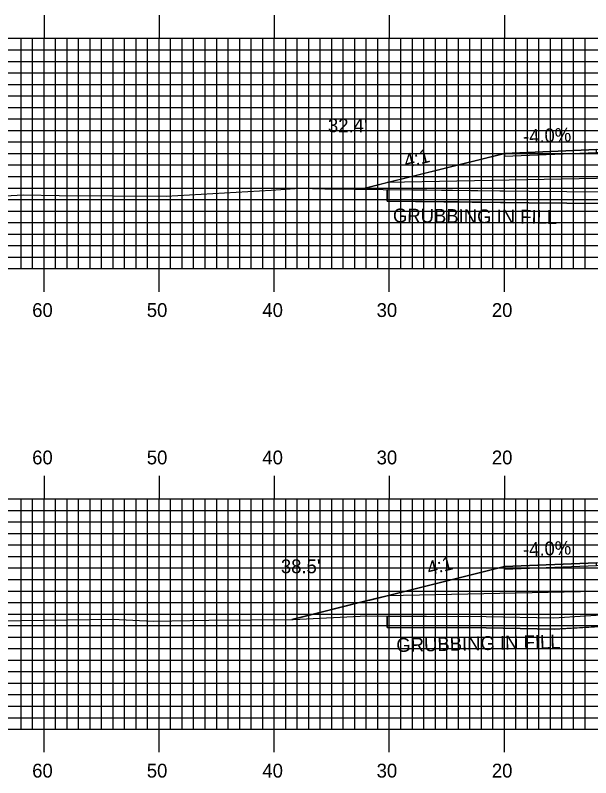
# Model space of a CAD drawing. Extents: x 1777925 to 1778268, y 442591 to 442811.
# Drawn here: x 1778028.3 to 1778078.3, y 442689.4 to 442755.7 of the extents above; entities that cross this region are included whole.
import ezdxf

# ---------------------------------------------------------------- set-up
doc = ezdxf.new("R2010")
doc.units = 0
for name, color, linetype in [('ANNOTATION', 7, 'Continuous'), ('D_Roadway_Centerline', 7, 'Continuous'), ('D_Roadway_Edge_Shoulder', 7, 'Continuous'), ('D_Roadway_SlopeLines', 7, 'Continuous'), ('D_Roadway_SubGrade', 7, 'Continuous'), ('D_Text_Standard', 7, 'Continuous'), ('GRUBBING IN FILL', 7, 'Continuous'), ('H_V ANNOTATION', 7, 'Continuous'), ('MAJOR', 7, 'Continuous'), ('MINOR', 7, 'Continuous'), ('S_Roadway_Centerline', 7, 'Continuous')]:
    doc.layers.add(name, color=color, linetype=linetype)

msp = doc.modelspace()

# ---------------------------------------------------------------- linework, layer by layer
at = {"layer": 'D_Roadway_Centerline'}
for points in [[(1778058.344, 442740.566), (1778060.616, 442741.134), (1778070.79, 442743.677), (1778078.79, 442743.997), (1778090.789, 442744.237), (1778090.79, 442744.237), (1778097.486, 442744.103), (1778102.79, 442743.997), (1778107.608, 442743.804), (1778110.79, 442743.677), (1778120.964, 442741.134), (1778124.306, 442740.299)], [(1778054.753, 442740.615), (1778054.761, 442740.615)], [(1778052.326, 442703.186), (1778053.506, 442703.481), (1778058.79, 442704.802), (1778059.096, 442704.879), (1778060.616, 442705.259), (1778065.395, 442706.454), (1778070.79, 442707.802), (1778078.79, 442708.122), (1778088.92, 442708.325), (1778090.79, 442708.362), (1778102.79, 442708.122), (1778108.283, 442707.902), (1778110.79, 442707.802), (1778120.964, 442705.259), (1778126.218, 442703.946)]]:
    msp.add_lwpolyline(points, dxfattribs=at)
at = {"layer": 'D_Roadway_Edge_Shoulder'}
for points in [[(1778078.79, 442743.997), (1778070.79, 442743.677), (1778070.79, 442743.427), (1778078.79, 442743.747)], [(1778078.79, 442708.122), (1778070.79, 442707.802), (1778070.79, 442707.552), (1778078.79, 442707.872)]]:
    msp.add_lwpolyline(points, close=True, dxfattribs=at)
at = {"layer": 'D_Roadway_SlopeLines'}
for points in [[(1778070.79, 442743.677), (1778058.344, 442740.566)], [(1778070.79, 442707.802), (1778060.616, 442705.259), (1778058.79, 442704.802), (1778052.326, 442703.186)]]:
    msp.add_lwpolyline(points, dxfattribs=at)
at = {"layer": 'D_Roadway_SubGrade'}
for points in [[(1778078.79, 442741.497), (1778060.616, 442741.134), (1778070.79, 442743.677), (1778070.79, 442743.427), (1778078.79, 442743.747), (1778090.79, 442743.987), (1778102.79, 442743.747), (1778110.79, 442743.427), (1778110.79, 442743.677), (1778120.964, 442741.134), (1778102.79, 442741.497), (1778090.79, 442741.737)], [(1778078.79, 442705.622), (1778060.616, 442705.259), (1778070.79, 442707.802), (1778070.79, 442707.552), (1778078.79, 442707.872), (1778090.79, 442708.112), (1778102.79, 442707.872), (1778110.79, 442707.552), (1778110.79, 442707.802), (1778120.964, 442705.259), (1778102.79, 442705.622), (1778090.79, 442705.862)]]:
    msp.add_lwpolyline(points, close=True, dxfattribs=at)
at = {"layer": 'GRUBBING IN FILL'}
for p, q in [((1778060.616, 442740.537), (1778060.616, 442739.537)), ((1778060.616, 442740.537), (1778060.616, 442739.537)), ((1778060.616, 442703.49), (1778060.616, 442702.49)), ((1778060.616, 442703.49), (1778060.616, 442702.49))]:
    msp.add_line(p, q, dxfattribs=at)
for points in [[(1778060.616, 442740.537), (1778064.057, 442740.494), (1778072.934, 442740.381), (1778076.219, 442740.352), (1778079.504, 442740.324), (1778083.5, 442740.316), (1778087.496, 442740.308), (1778090.79, 442740.292), (1778090.79, 442739.292), (1778087.492, 442739.308), (1778076.211, 442739.352), (1778072.923, 442739.381), (1778066.77, 442739.459), (1778060.616, 442739.537)], [(1778060.616, 442740.537), (1778064.057, 442740.494), (1778072.934, 442740.381), (1778076.219, 442740.352), (1778079.504, 442740.324), (1778083.5, 442740.316), (1778087.496, 442740.308), (1778090.79, 442740.292), (1778090.79, 442739.292), (1778087.492, 442739.308), (1778076.211, 442739.352), (1778072.923, 442739.381), (1778066.77, 442739.459), (1778060.616, 442739.537)], [(1778060.616, 442702.49), (1778060.616, 442703.49), (1778064.022, 442703.478), (1778069.212, 442703.46), (1778075.082, 442703.34), (1778080.576, 442703.67), (1778085.956, 442703.697), (1778090.79, 442703.721), (1778090.79, 442702.721), (1778085.958, 442702.697), (1778080.608, 442702.67), (1778077.855, 442702.505), (1778075.101, 442702.339), (1778072.151, 442702.4), (1778069.2, 442702.46)], [(1778060.616, 442702.49), (1778060.616, 442703.49), (1778064.022, 442703.478), (1778069.212, 442703.46), (1778075.082, 442703.34), (1778080.576, 442703.67), (1778085.956, 442703.697), (1778090.79, 442703.721), (1778090.79, 442702.721), (1778085.958, 442702.697), (1778080.608, 442702.67), (1778077.855, 442702.505), (1778075.101, 442702.339), (1778072.151, 442702.4), (1778069.2, 442702.46)]]:
    msp.add_lwpolyline(points, close=True, dxfattribs=at)
for points in [[(1778060.616, 442739.537), (1778072.923, 442739.381), (1778079.499, 442739.324), (1778087.492, 442739.308), (1778097.437, 442739.262), (1778101.244, 442739.246), (1778110.991, 442739.24), (1778120.964, 442739.288)], [(1778060.616, 442739.537), (1778072.923, 442739.381), (1778079.499, 442739.324), (1778087.492, 442739.308), (1778097.437, 442739.262), (1778101.244, 442739.246), (1778110.991, 442739.24), (1778120.964, 442739.288)], [(1778060.616, 442702.49), (1778069.2, 442702.46), (1778075.101, 442702.339), (1778080.608, 442702.67), (1778091.308, 442702.724), (1778097.749, 442702.34), (1778103.966, 442702.493), (1778110.139, 442702.686), (1778116.078, 442702.822), (1778120.964, 442702.882)], [(1778060.616, 442702.49), (1778069.2, 442702.46), (1778075.101, 442702.339), (1778080.608, 442702.67), (1778091.308, 442702.724), (1778097.749, 442702.34), (1778103.966, 442702.493), (1778110.139, 442702.686), (1778116.078, 442702.822), (1778120.964, 442702.882)]]:
    msp.add_lwpolyline(points, dxfattribs=at)
at = {"layer": 'MAJOR'}
for p, q in [((1778030.79, 442755.669), (1778030.79, 442753.665)), ((1778040.79, 442755.669), (1778040.79, 442753.665)), ((1778050.79, 442755.669), (1778050.79, 442753.665)), ((1778060.79, 442755.669), (1778060.79, 442753.665)), ((1778070.79, 442755.669), (1778070.79, 442753.665)), ((1777950.79, 442753.665), (1778230.79, 442753.665)), ((1777950.79, 442753.665), (1778230.79, 442753.665)), ((1778030.79, 442733.665), (1778030.79, 442753.665)), ((1778040.79, 442733.665), (1778040.79, 442753.665)), ((1778050.79, 442733.665), (1778050.79, 442753.665)), ((1778060.79, 442733.665), (1778060.79, 442753.665)), ((1778070.79, 442733.665), (1778070.79, 442753.665)), ((1777950.79, 442748.665), (1778230.79, 442748.665)), ((1777950.79, 442743.665), (1778230.79, 442743.665)), ((1777950.79, 442738.665), (1778230.79, 442738.665)), ((1777950.79, 442733.665), (1778230.79, 442733.665)), ((1777950.79, 442733.665), (1778230.79, 442733.665)), ((1778030.79, 442731.661), (1778030.79, 442733.665)), ((1778040.79, 442731.661), (1778040.79, 442733.665)), ((1778050.79, 442731.661), (1778050.79, 442733.665)), ((1778060.79, 442731.661), (1778060.79, 442733.665)), ((1778070.79, 442731.661), (1778070.79, 442733.665)), ((1778030.79, 442715.669), (1778030.79, 442713.665)), ((1778040.79, 442715.669), (1778040.79, 442713.665)), ((1778050.79, 442715.669), (1778050.79, 442713.665)), ((1778060.79, 442715.669), (1778060.79, 442713.665)), ((1778070.79, 442715.669), (1778070.79, 442713.665)), ((1777950.79, 442713.665), (1778230.79, 442713.665)), ((1777950.79, 442713.665), (1778230.79, 442713.665)), ((1778030.79, 442693.665), (1778030.79, 442713.665)), ((1778040.79, 442693.665), (1778040.79, 442713.665)), ((1778050.79, 442693.665), (1778050.79, 442713.665)), ((1778060.79, 442693.665), (1778060.79, 442713.665)), ((1778070.79, 442693.665), (1778070.79, 442713.665)), ((1777950.79, 442708.665), (1778230.79, 442708.665)), ((1777950.79, 442703.665), (1778230.79, 442703.665)), ((1777950.79, 442698.665), (1778230.79, 442698.665)), ((1777950.79, 442693.665), (1778230.79, 442693.665)), ((1777950.79, 442693.665), (1778230.79, 442693.665)), ((1778030.79, 442691.661), (1778030.79, 442693.665)), ((1778040.79, 442691.661), (1778040.79, 442693.665)), ((1778050.79, 442691.661), (1778050.79, 442693.665)), ((1778060.79, 442691.661), (1778060.79, 442693.665)), ((1778070.79, 442691.661), (1778070.79, 442693.665))]:
    msp.add_line(p, q, dxfattribs=at)
at = {"layer": 'MINOR'}
for p, q in [((1778028.79, 442733.665), (1778028.79, 442753.665)), ((1778029.79, 442733.665), (1778029.79, 442753.665)), ((1778031.79, 442733.665), (1778031.79, 442753.665)), ((1778032.79, 442733.665), (1778032.79, 442753.665)), ((1778033.79, 442733.665), (1778033.79, 442753.665)), ((1778034.79, 442733.665), (1778034.79, 442753.665)), ((1778035.79, 442733.665), (1778035.79, 442753.665)), ((1778036.79, 442733.665), (1778036.79, 442753.665)), ((1778037.79, 442733.665), (1778037.79, 442753.665)), ((1778038.79, 442733.665), (1778038.79, 442753.665)), ((1778039.79, 442733.665), (1778039.79, 442753.665)), ((1778041.79, 442733.665), (1778041.79, 442753.665)), ((1778042.79, 442733.665), (1778042.79, 442753.665)), ((1778043.79, 442733.665), (1778043.79, 442753.665)), ((1778044.79, 442733.665), (1778044.79, 442753.665)), ((1778045.79, 442733.665), (1778045.79, 442753.665)), ((1778046.79, 442733.665), (1778046.79, 442753.665)), ((1778047.79, 442733.665), (1778047.79, 442753.665)), ((1778048.79, 442733.665), (1778048.79, 442753.665)), ((1778049.79, 442733.665), (1778049.79, 442753.665)), ((1778051.79, 442733.665), (1778051.79, 442753.665)), ((1778052.79, 442733.665), (1778052.79, 442753.665)), ((1778053.79, 442733.665), (1778053.79, 442753.665)), ((1778054.79, 442733.665), (1778054.79, 442753.665)), ((1778055.79, 442733.665), (1778055.79, 442753.665)), ((1778056.79, 442733.665), (1778056.79, 442753.665)), ((1778057.79, 442733.665), (1778057.79, 442753.665)), ((1778058.79, 442733.665), (1778058.79, 442753.665)), ((1778059.79, 442733.665), (1778059.79, 442753.665)), ((1778061.79, 442733.665), (1778061.79, 442753.665)), ((1778062.79, 442733.665), (1778062.79, 442753.665)), ((1778063.79, 442733.665), (1778063.79, 442753.665)), ((1778064.79, 442733.665), (1778064.79, 442753.665)), ((1778065.79, 442733.665), (1778065.79, 442753.665)), ((1778066.79, 442733.665), (1778066.79, 442753.665)), ((1778067.79, 442733.665), (1778067.79, 442753.665)), ((1778068.79, 442733.665), (1778068.79, 442753.665)), ((1778069.79, 442733.665), (1778069.79, 442753.665)), ((1778071.79, 442733.665), (1778071.79, 442753.665)), ((1778072.79, 442733.665), (1778072.79, 442753.665)), ((1778073.79, 442733.665), (1778073.79, 442753.665)), ((1778074.79, 442733.665), (1778074.79, 442753.665)), ((1778075.79, 442733.665), (1778075.79, 442753.665)), ((1778076.79, 442733.665), (1778076.79, 442753.665)), ((1778077.79, 442733.665), (1778077.79, 442753.665)), ((1777950.79, 442752.665), (1778230.79, 442752.665)), ((1777950.79, 442751.665), (1778230.79, 442751.665)), ((1777950.79, 442750.665), (1778230.79, 442750.665)), ((1777950.79, 442749.665), (1778230.79, 442749.665)), ((1777950.79, 442747.665), (1778230.79, 442747.665)), ((1777950.79, 442746.665), (1778230.79, 442746.665)), ((1777950.79, 442745.665), (1778230.79, 442745.665)), ((1777950.79, 442744.665), (1778230.79, 442744.665)), ((1777950.79, 442742.665), (1778230.79, 442742.665)), ((1777950.79, 442741.665), (1778230.79, 442741.665)), ((1777950.79, 442740.665), (1778230.79, 442740.665)), ((1777950.79, 442739.665), (1778230.79, 442739.665)), ((1777950.79, 442737.665), (1778230.79, 442737.665)), ((1777950.79, 442736.665), (1778230.79, 442736.665)), ((1777950.79, 442735.665), (1778230.79, 442735.665)), ((1777950.79, 442734.665), (1778230.79, 442734.665)), ((1778028.79, 442693.665), (1778028.79, 442713.665)), ((1778029.79, 442693.665), (1778029.79, 442713.665)), ((1778031.79, 442693.665), (1778031.79, 442713.665)), ((1778032.79, 442693.665), (1778032.79, 442713.665)), ((1778033.79, 442693.665), (1778033.79, 442713.665)), ((1778034.79, 442693.665), (1778034.79, 442713.665)), ((1778035.79, 442693.665), (1778035.79, 442713.665)), ((1778036.79, 442693.665), (1778036.79, 442713.665)), ((1778037.79, 442693.665), (1778037.79, 442713.665)), ((1778038.79, 442693.665), (1778038.79, 442713.665)), ((1778039.79, 442693.665), (1778039.79, 442713.665)), ((1778041.79, 442693.665), (1778041.79, 442713.665)), ((1778042.79, 442693.665), (1778042.79, 442713.665)), ((1778043.79, 442693.665), (1778043.79, 442713.665)), ((1778044.79, 442693.665), (1778044.79, 442713.665)), ((1778045.79, 442693.665), (1778045.79, 442713.665)), ((1778046.79, 442693.665), (1778046.79, 442713.665)), ((1778047.79, 442693.665), (1778047.79, 442713.665)), ((1778048.79, 442693.665), (1778048.79, 442713.665)), ((1778049.79, 442693.665), (1778049.79, 442713.665)), ((1778051.79, 442693.665), (1778051.79, 442713.665)), ((1778052.79, 442693.665), (1778052.79, 442713.665)), ((1778053.79, 442693.665), (1778053.79, 442713.665)), ((1778054.79, 442693.665), (1778054.79, 442713.665)), ((1778055.79, 442693.665), (1778055.79, 442713.665)), ((1778056.79, 442693.665), (1778056.79, 442713.665)), ((1778057.79, 442693.665), (1778057.79, 442713.665)), ((1778058.79, 442693.665), (1778058.79, 442713.665)), ((1778059.79, 442693.665), (1778059.79, 442713.665)), ((1778061.79, 442693.665), (1778061.79, 442713.665)), ((1778062.79, 442693.665), (1778062.79, 442713.665)), ((1778063.79, 442693.665), (1778063.79, 442713.665)), ((1778064.79, 442693.665), (1778064.79, 442713.665)), ((1778065.79, 442693.665), (1778065.79, 442713.665)), ((1778066.79, 442693.665), (1778066.79, 442713.665)), ((1778067.79, 442693.665), (1778067.79, 442713.665)), ((1778068.79, 442693.665), (1778068.79, 442713.665)), ((1778069.79, 442693.665), (1778069.79, 442713.665)), ((1778071.79, 442693.665), (1778071.79, 442713.665)), ((1778072.79, 442693.665), (1778072.79, 442713.665)), ((1778073.79, 442693.665), (1778073.79, 442713.665)), ((1778074.79, 442693.665), (1778074.79, 442713.665)), ((1778075.79, 442693.665), (1778075.79, 442713.665)), ((1778076.79, 442693.665), (1778076.79, 442713.665)), ((1778077.79, 442693.665), (1778077.79, 442713.665)), ((1777950.79, 442712.665), (1778230.79, 442712.665)), ((1777950.79, 442711.665), (1778230.79, 442711.665)), ((1777950.79, 442710.665), (1778230.79, 442710.665)), ((1777950.79, 442709.665), (1778230.79, 442709.665)), ((1777950.79, 442707.665), (1778230.79, 442707.665)), ((1777950.79, 442706.665), (1778230.79, 442706.665)), ((1777950.79, 442705.665), (1778230.79, 442705.665)), ((1777950.79, 442704.665), (1778230.79, 442704.665)), ((1777950.79, 442702.665), (1778230.79, 442702.665)), ((1777950.79, 442701.665), (1778230.79, 442701.665)), ((1777950.79, 442700.665), (1778230.79, 442700.665)), ((1777950.79, 442699.665), (1778230.79, 442699.665)), ((1777950.79, 442697.665), (1778230.79, 442697.665)), ((1777950.79, 442696.665), (1778230.79, 442696.665)), ((1777950.79, 442695.665), (1778230.79, 442695.665)), ((1777950.79, 442694.665), (1778230.79, 442694.665))]:
    msp.add_line(p, q, dxfattribs=at)
at = {"layer": 'S_Roadway_Centerline'}
for points in [[(1777950.79, 442738.966), (1777955.192, 442738.991), (1777965.367, 442739.306), (1777978.504, 442739.313), (1777987.996, 442739.104), (1778001.991, 442739.387), (1778011.67, 442739.438), (1778026.292, 442739.932), (1778029.016, 442740.075), (1778032.096, 442740.028), (1778041.415, 442739.945), (1778050.527, 442740.466), (1778053.017, 442740.649), (1778055.18, 442740.606), (1778072.934, 442740.381), (1778079.504, 442740.324), (1778087.496, 442740.308), (1778097.442, 442740.262), (1778101.246, 442740.246), (1778110.988, 442740.24), (1778123.356, 442740.3), (1778145.529, 442740.267)], [(1778020.918, 442702.982), (1778036.728, 442703.212), (1778040.284, 442703.05), (1778045.106, 442703.135), (1778052.437, 442703.187), (1778058.831, 442703.496), (1778069.212, 442703.46), (1778075.082, 442703.34), (1778080.576, 442703.67), (1778091.336, 442703.724), (1778097.767, 442703.341), (1778103.938, 442703.493), (1778110.111, 442703.685), (1778116.06, 442703.822), (1778126.597, 442703.95), (1778139.237, 442703.725)]]:
    msp.add_lwpolyline(points, dxfattribs=at)

# ---------------------------------------------------------------- texts
at = {"layer": 'ANNOTATION'}
for s, rotation, p in [('-4.0%', 2.29053, (1778072.422, 442744.544)), ('4:1', 14.03473, (1778062.238, 442742.401)), ('-4.0%', 2.29053, (1778072.422, 442708.669)), ('4:1', 14.03386, (1778064.238, 442707.026))]:
    msp.add_text(s, height=1.2, rotation=rotation, dxfattribs=at).set_placement(p)
at = {"layer": 'D_Text_Standard'}
for s, p in [("32.4'", (1778055.458, 442745.505)), ("38.5'", (1778051.369, 442707.211))]:
    msp.add_text(s, height=1.2, dxfattribs=at).set_placement(p)
at = {"layer": 'GRUBBING IN FILL'}
for rotation, p in [(359.43024, (1778061.098, 442737.687)), (1.25379, (1778061.411, 442700.368))]:
    msp.add_text('GRUBBING IN FILL', height=1.2, rotation=rotation, dxfattribs=at).set_placement(p)
at = {"layer": 'H_V ANNOTATION'}
for s, p in [('60', (1778029.762, 442729.465)), ('50', (1778039.719, 442729.465)), ('40', (1778049.762, 442729.465)), ('30', (1778059.687, 442729.465)), ('20', (1778069.698, 442729.465)), ('60', (1778029.762, 442716.665)), ('50', (1778039.719, 442716.665)), ('40', (1778049.762, 442716.665)), ('30', (1778059.687, 442716.665)), ('20', (1778069.698, 442716.665)), ('60', (1778029.762, 442689.465)), ('50', (1778039.719, 442689.465)), ('40', (1778049.762, 442689.465)), ('30', (1778059.687, 442689.465)), ('20', (1778069.698, 442689.465))]:
    msp.add_text(s, height=1.2, dxfattribs=at).set_placement(p)

doc.saveas('drawing.dxf')
